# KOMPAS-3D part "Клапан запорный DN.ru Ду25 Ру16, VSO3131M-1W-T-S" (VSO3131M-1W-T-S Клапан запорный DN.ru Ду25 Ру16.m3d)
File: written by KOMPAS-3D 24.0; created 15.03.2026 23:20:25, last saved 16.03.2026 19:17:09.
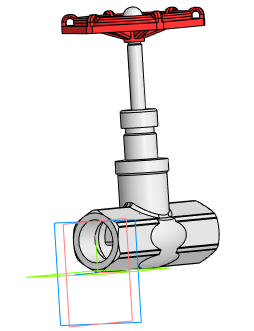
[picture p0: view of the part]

Document properties: Автор: artiomk228874@gmail.com; Полное имя файла: VSO3131M-1W-T-S Клапан запорный DN.ru Ду25 Ру16.cdw

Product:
- Body: Тело 1  | qty 1
    Масса: 0.324398
- Part/product: Клапан запорный DN.ru Ду25 Ру16  | designation VSO3131M-1W-T-S
    Масса: 0.55
    Раздел спецификации: Прочие изделия
    Форматы листов документа: A2
    Примечание: D100-03671
    additional columns: 94d3474e-3e6e-4ddd-ad0b-ef51eb5e31da; VSO3131M-1W-T-S; Сталь 10 ГОСТ 1050-2013; artiomk228874@gmail.com; c; Шероховатость не задана; Да

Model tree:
1. Операция без истории:1

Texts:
  VSO3131M-1W-T-S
